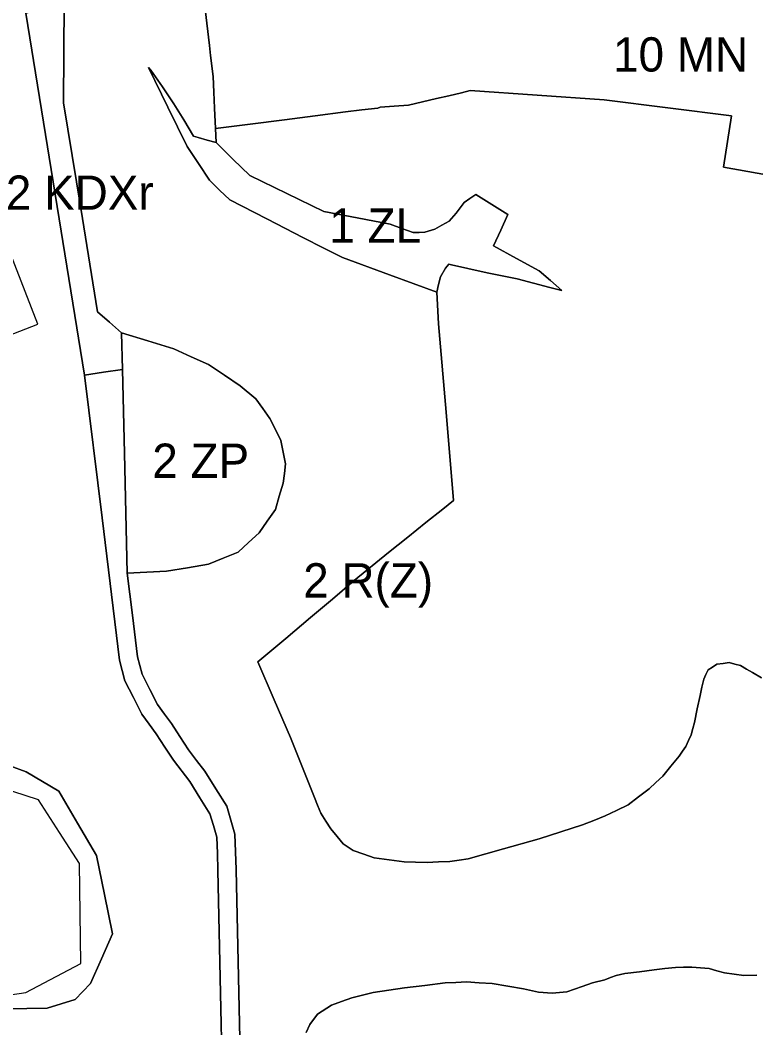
# Model space of a CAD drawing. Extents: x 7422252 to 7424226, y 5538569 to 5540380.
# Drawn here: x 7422919.5 to 7423241.3, y 5539103.9 to 5539544.8 of the extents above; entities that cross this region are included whole.
import ezdxf

# ---------------------------------------------------------------- set-up
doc = ezdxf.new("R2010")
doc.units = 0
for name, color, linetype in [('linie_rozgraniczajace', 7, 'Continuous'), ('linie_zabudowy_nieprzekraczalne', 7, 'Continuous'), ('oznaczenia_przeznaczen', 7, 'Continuous')]:
    doc.layers.add(name, color=color, linetype=linetype)

msp = doc.modelspace()

# ---------------------------------------------------------------- linework, layer by layer
at = {"layer": 'linie_rozgraniczajace'}
for points in [[(7423004.5, 5539506.3), (7423004.19, 5539513.23), (7423003.88, 5539520.17), (7423002.82, 5539529.33), (7423002.33, 5539533.66), (7423001.17, 5539543.48), (7423000.01, 5539553.3), (7422999.1, 5539558.79), (7422998.19, 5539564.28), (7422996.71, 5539573.16), (7422995.24, 5539582.03), (7422993.39, 5539589.32)], [(7422938.52, 5539508.56), (7422938.66, 5539530.56), (7422938.8, 5539552.56)], [(7423000.01, 5539553.3), (7423001.17, 5539543.48), (7423002.33, 5539533.66), (7423002.82, 5539529.33), (7423003.88, 5539520.17), (7423004.19, 5539513.23), (7423004.5, 5539506.3), (7423005, 5539497.42), (7423005.22, 5539491.17), (7423001.32, 5539492.3), (7422997.42, 5539493.44), (7422995.33, 5539494.06), (7422991.06, 5539501.14), (7422986.79, 5539508.21), (7422981.71, 5539515.52), (7422976.63, 5539522.84), (7422975.66, 5539524.01), (7422984.14, 5539506.72), (7422992.61, 5539489.43), (7422997.46, 5539482.11), (7423002.31, 5539474.78), (7423006.77, 5539470.43), (7423011.22, 5539466.09), (7423027.37, 5539457.82), (7423043.51, 5539449.56), (7423052.01, 5539445.2), (7423060.51, 5539440.85), (7423081.14, 5539433.34), (7423101.77, 5539425.82), (7423102.5, 5539411.86), (7423105.79, 5539373.21), (7423109.07, 5539334.55), (7423104.38, 5539330.82), (7423097.04, 5539325), (7423089.05, 5539318.54), (7423080.62, 5539311.82), (7423065.6, 5539299.62), (7423056.08, 5539291.39), (7423046.57, 5539283.46), (7423035.78, 5539274.23), (7423023.45, 5539264.05), (7423030.59, 5539247.47), (7423037.74, 5539230.89), (7423042.97, 5539217.8), (7423048.21, 5539204.7), (7423049.64, 5539201.26), (7423051.07, 5539197.82), (7423053.22, 5539194.37), (7423055.37, 5539190.92), (7423058.12, 5539187.65), (7423060.87, 5539184.39), (7423063.06, 5539182.95), (7423065.25, 5539181.51), (7423069.78, 5539179.9), (7423074.3, 5539178.3), (7423080.88, 5539177.41), (7423087.47, 5539176.52), (7423092.49, 5539176.39), (7423097.51, 5539176.26), (7423102.51, 5539176.51), (7423107.51, 5539176.75), (7423111.48, 5539177.32), (7423115.45, 5539177.89), (7423131, 5539182.28), (7423146.55, 5539186.66), (7423156.04, 5539189.67), (7423165.54, 5539192.67), (7423170.45, 5539194.67), (7423175.37, 5539196.67), (7423180.42, 5539199.06), (7423185.46, 5539201.44), (7423190.06, 5539204.99), (7423194.66, 5539208.54), (7423197.64, 5539211.3), (7423200.61, 5539214.07), (7423204.18, 5539218.43), (7423207.75, 5539222.8), (7423209.26, 5539224.9), (7423210.77, 5539227.01), (7423211.9, 5539229.58), (7423213.03, 5539232.14), (7423213.77, 5539234.81), (7423214.51, 5539237.49), (7423215.74, 5539243.4), (7423216.97, 5539249.32)], [(7422921.99, 5539547.81), (7422934.85, 5539468.63), (7422947.7, 5539389.45), (7422955.33, 5539327.07), (7422962.95, 5539264.69), (7422964.14, 5539260.23), (7422965.33, 5539255.76), (7422969.05, 5539248.43), (7422972.78, 5539241.1), (7422975.92, 5539236.81), (7422979.06, 5539232.51), (7422982.8, 5539226.73), (7422986.54, 5539220.95), (7422993.66, 5539211.67), (7422998.1, 5539204.6), (7423002.54, 5539197.53), (7423004.02, 5539192.46), (7423005.49, 5539187.39), (7423005.76, 5539180.15), (7423006.02, 5539172.9), (7423007.01, 5539125.74), (7423008, 5539078.57)], [(7423248.47, 5539476.61), (7423237.81, 5539478.49), (7423227.15, 5539480.37), (7423228.95, 5539491.62), (7423230.75, 5539502.87), (7423202.9, 5539506.36), (7423175.05, 5539509.86), (7423145.73, 5539511.95), (7423116.4, 5539514.04), (7423112.56, 5539512.95), (7423107.09, 5539511.68), (7423101.62, 5539510.41), (7423095.47, 5539508.99), (7423089.33, 5539507.56), (7423083.15, 5539507.1), (7423076.96, 5539506.64), (7423075.99, 5539506.28), (7423068.91, 5539505.45), (7423061.83, 5539504.62), (7423048.5, 5539502.85), (7423035.17, 5539501.08), (7423020.08, 5539499.25), (7423005, 5539497.42), (7423004.5, 5539506.3)], [(7423106.97, 5539438.01), (7423108.25, 5539437.72), (7423115.39, 5539436.08), (7423123.81, 5539434.15), (7423130.37, 5539432.83), (7423136.93, 5539431.52), (7423144.08, 5539429.67), (7423151.22, 5539427.83), (7423156.45, 5539426.55), (7423151.49, 5539430.81), (7423146.54, 5539435.07), (7423136.57, 5539440.53), (7423126.6, 5539445.99), (7423129.73, 5539452.83), (7423132.87, 5539459.68), (7423125.82, 5539464.11), (7423118.78, 5539468.55), (7423116.23, 5539466.79), (7423113.69, 5539465.03), (7423111.98, 5539462.7), (7423110.27, 5539460.37), (7423107.21, 5539456.77), (7423104.03, 5539455.01), (7423100.85, 5539453.26), (7423096.52, 5539451.95), (7423093.98, 5539451.92), (7423091.44, 5539451.88), (7423086.42, 5539453.66), (7423081.4, 5539455.44), (7423066.87, 5539458.24), (7423052.35, 5539461.05), (7423036.17, 5539468.93), (7423019.99, 5539476.81), (7423012.6, 5539483.99), (7423005.22, 5539491.17), (7423005, 5539497.42), (7423020.08, 5539499.25), (7423035.17, 5539501.08), (7423048.5, 5539502.85), (7423061.83, 5539504.62), (7423068.91, 5539505.45), (7423075.99, 5539506.28), (7423076.96, 5539506.64), (7423083.15, 5539507.1), (7423089.33, 5539507.56), (7423095.47, 5539508.99), (7423101.62, 5539510.41), (7423107.09, 5539511.68), (7423112.56, 5539512.95), (7423116.4, 5539514.04), (7423145.73, 5539511.95), (7423175.05, 5539509.86), (7423202.9, 5539506.36), (7423230.75, 5539502.87), (7423228.95, 5539491.62), (7423227.15, 5539480.37), (7423237.81, 5539478.49), (7423248.47, 5539476.61)], [(7423015.99, 5539079), (7423015, 5539126.07), (7423014.02, 5539173.13), (7423013.73, 5539180.9), (7423013.45, 5539188.67), (7423011.68, 5539194.76), (7423009.91, 5539200.84), (7423005.07, 5539208.54), (7423000.24, 5539216.24), (7422996.66, 5539220.9), (7422993.08, 5539225.56), (7422989.37, 5539231.3), (7422985.66, 5539237.05), (7422982.64, 5539241.17), (7422979.62, 5539245.3), (7422976.23, 5539251.97), (7422972.84, 5539258.63), (7422971.83, 5539262.42), (7422970.83, 5539266.21), (7422968.59, 5539284.48), (7422966.36, 5539302.75), (7422974.97, 5539303.23), (7422983.57, 5539303.71), (7422992.71, 5539305.21), (7423001.84, 5539306.71), (7423008.37, 5539309.36), (7423014.89, 5539312.02), (7423019.44, 5539316.26), (7423023.99, 5539320.51), (7423027.56, 5539325.61), (7423031.13, 5539330.71), (7423032.82, 5539336.47), (7423034.52, 5539342.24), (7423035.08, 5539346.43), (7423035.64, 5539350.62), (7423034.62, 5539355.73), (7423033.59, 5539360.85), (7423031.19, 5539365.67), (7423028.78, 5539370.49), (7423025.69, 5539374.8), (7423022.6, 5539379.11), (7423015.76, 5539384.84), (7423008.86, 5539389.49), (7423001.95, 5539394.14), (7422994.37, 5539397.52), (7422986.78, 5539400.9), (7422975.31, 5539404.44), (7422963.84, 5539407.98), (7422958.59, 5539412.56), (7422953.34, 5539417.13), (7422945.97, 5539462.52), (7422938.52, 5539508.56)], [(7423243.77, 5539256.98), (7423239.86, 5539259.34), (7423237.22, 5539260.87), (7423234.59, 5539262.4), (7423232.13, 5539263.06), (7423229.68, 5539263.73), (7423226.98, 5539263.34), (7423224.28, 5539262.96), (7423222.38, 5539261.73), (7423220.47, 5539260.49), (7423219.52, 5539258.51), (7423218.56, 5539256.52), (7423217.77, 5539252.92), (7423216.97, 5539249.32), (7423215.74, 5539243.4), (7423214.51, 5539237.49), (7423213.77, 5539234.81), (7423213.03, 5539232.14), (7423211.9, 5539229.58), (7423210.77, 5539227.01), (7423209.26, 5539224.9), (7423207.75, 5539222.8), (7423204.18, 5539218.43), (7423200.61, 5539214.07), (7423197.64, 5539211.3), (7423194.66, 5539208.54), (7423190.06, 5539204.99), (7423185.46, 5539201.44), (7423180.42, 5539199.06), (7423175.37, 5539196.67), (7423170.45, 5539194.67), (7423165.54, 5539192.67), (7423156.04, 5539189.67), (7423146.55, 5539186.66), (7423131, 5539182.28), (7423115.45, 5539177.89), (7423111.48, 5539177.32), (7423107.51, 5539176.75), (7423102.51, 5539176.51), (7423097.51, 5539176.26), (7423092.49, 5539176.39), (7423087.47, 5539176.52), (7423080.88, 5539177.41), (7423074.3, 5539178.3), (7423069.78, 5539179.9), (7423065.25, 5539181.51), (7423063.06, 5539182.95), (7423060.87, 5539184.39), (7423058.12, 5539187.65), (7423055.37, 5539190.92), (7423053.22, 5539194.37), (7423051.07, 5539197.82), (7423049.64, 5539201.26), (7423048.21, 5539204.7), (7423042.97, 5539217.8), (7423037.74, 5539230.89), (7423030.59, 5539247.47), (7423023.45, 5539264.05), (7423035.78, 5539274.23), (7423046.57, 5539283.46), (7423056.08, 5539291.39), (7423065.6, 5539299.62), (7423080.62, 5539311.82), (7423089.05, 5539318.54), (7423097.04, 5539325), (7423104.38, 5539330.82), (7423109.07, 5539334.55), (7423105.79, 5539373.21), (7423102.5, 5539411.86), (7423101.77, 5539425.82), (7423102.58, 5539429.14), (7423103.39, 5539432.45), (7423105.63, 5539436.29), (7423106.97, 5539438.01)], [(7423008, 5539078.57), (7423007.01, 5539125.74), (7423006.02, 5539172.9), (7423005.76, 5539180.15), (7423005.49, 5539187.39), (7423004.02, 5539192.46), (7423002.54, 5539197.53), (7422998.1, 5539204.6), (7422993.66, 5539211.67), (7422986.54, 5539220.95), (7422982.8, 5539226.73), (7422979.06, 5539232.51), (7422975.92, 5539236.81), (7422972.78, 5539241.1), (7422969.05, 5539248.43), (7422965.33, 5539255.76), (7422964.14, 5539260.23), (7422962.95, 5539264.69), (7422955.33, 5539327.07), (7422947.7, 5539389.45), (7422955.96, 5539390.69), (7422964.22, 5539391.93), (7422965.1, 5539355.37), (7422966.36, 5539302.75), (7422968.59, 5539284.48), (7422970.83, 5539266.21), (7422971.83, 5539262.42), (7422972.84, 5539258.63), (7422976.23, 5539251.97), (7422979.62, 5539245.3), (7422982.64, 5539241.17), (7422985.66, 5539237.05), (7422989.37, 5539231.3), (7422993.08, 5539225.56), (7422996.66, 5539220.9), (7423000.24, 5539216.24), (7423005.07, 5539208.54), (7423009.91, 5539200.84), (7423011.68, 5539194.76), (7423013.45, 5539188.67), (7423013.73, 5539180.9), (7423014.02, 5539173.13), (7423015, 5539126.07), (7423015.99, 5539079)], [(7423216.97, 5539249.32), (7423217.77, 5539252.92), (7423218.56, 5539256.52), (7423219.52, 5539258.51), (7423220.47, 5539260.49), (7423222.38, 5539261.73), (7423224.28, 5539262.96), (7423226.98, 5539263.34), (7423229.68, 5539263.73), (7423232.13, 5539263.06), (7423234.59, 5539262.4), (7423237.22, 5539260.87), (7423239.86, 5539259.34), (7423243.77, 5539256.98)], [(7422914.99, 5539218.51), (7422922.15, 5539215.84), (7422929.26, 5539211.66), (7422936.38, 5539207.48), (7422944.62, 5539193.39), (7422952.87, 5539179.31), (7422956.35, 5539162.18), (7422959.83, 5539145.05), (7422955.05, 5539134.15), (7422950.27, 5539123.24), (7422946.9, 5539119.78), (7422943.53, 5539116.33), (7422937.4, 5539114.41), (7422931.27, 5539112.49), (7422913.58, 5539112.2)], [(7422913.58, 5539112.2), (7422931.27, 5539112.49), (7422937.4, 5539114.41), (7422943.53, 5539116.33), (7422946.9, 5539119.78), (7422950.27, 5539123.24), (7422955.05, 5539134.15), (7422959.83, 5539145.05), (7422956.35, 5539162.18), (7422952.87, 5539179.31), (7422944.62, 5539193.39), (7422936.38, 5539207.48), (7422929.26, 5539211.66), (7422922.15, 5539215.84), (7422914.99, 5539218.51)], [(7422879.52, 5539113.04), (7422921.94, 5539119.36), (7422946.07, 5539132.08), (7422945.46, 5539175.81), (7422936.7, 5539189.32), (7422927.51, 5539203.72), (7422910.87, 5539209.09)], [(7423044.56, 5539101.89), (7423046.22, 5539105.36), (7423049.58, 5539109.92), (7423055.7, 5539113.83), (7423060.11, 5539115.46), (7423064.53, 5539117.08), (7423073.96, 5539119.37), (7423080.78, 5539120.38), (7423087.61, 5539121.4), (7423096.54, 5539122.48), (7423105.47, 5539123.57), (7423110.11, 5539123.78), (7423114.76, 5539123.99), (7423120.35, 5539123.64), (7423125.95, 5539123.28), (7423132.79, 5539122.09), (7423139.64, 5539120.91), (7423146.31, 5539119.48), (7423152.26, 5539119.01), (7423155.45, 5539119.33), (7423158.65, 5539119.66), (7423162.04, 5539120.81), (7423165.42, 5539121.96), (7423169.91, 5539123.54), (7423175.22, 5539124.94), (7423177.69, 5539125.87), (7423180.16, 5539126.79), (7423182.06, 5539127.25), (7423183.96, 5539127.71), (7423190.44, 5539128.48), (7423196.91, 5539129.25), (7423201.52, 5539129.81), (7423206.13, 5539130.37), (7423209.75, 5539130.39), (7423213.38, 5539130.41), (7423217.16, 5539130.11), (7423220.93, 5539129.81), (7423224.28, 5539128.88), (7423227.64, 5539127.95), (7423231.83, 5539127.41), (7423236.02, 5539126.88), (7423241.8, 5539127.02)], [(7423241.8, 5539127.02), (7423236.02, 5539126.88), (7423231.83, 5539127.41), (7423227.64, 5539127.95), (7423224.28, 5539128.88), (7423220.93, 5539129.81), (7423217.16, 5539130.11), (7423213.38, 5539130.41), (7423209.75, 5539130.39), (7423206.13, 5539130.37), (7423201.52, 5539129.81), (7423196.91, 5539129.25), (7423190.44, 5539128.48), (7423183.96, 5539127.71), (7423182.06, 5539127.25), (7423180.16, 5539126.79), (7423177.69, 5539125.87), (7423175.22, 5539124.94), (7423169.91, 5539123.54), (7423165.42, 5539121.96), (7423162.04, 5539120.81), (7423158.65, 5539119.66)], [(7423158.65, 5539119.66), (7423155.45, 5539119.33), (7423152.26, 5539119.01), (7423146.31, 5539119.48), (7423139.64, 5539120.91), (7423132.79, 5539122.09), (7423125.95, 5539123.28), (7423120.35, 5539123.64), (7423114.76, 5539123.99), (7423110.11, 5539123.78), (7423105.47, 5539123.57), (7423096.54, 5539122.48), (7423087.61, 5539121.4), (7423080.78, 5539120.38), (7423073.96, 5539119.37), (7423064.53, 5539117.08), (7423060.11, 5539115.46), (7423055.7, 5539113.83), (7423049.58, 5539109.92), (7423046.22, 5539105.36), (7423044.56, 5539101.89)]]:
    msp.add_lwpolyline(points, dxfattribs=at)
for points in [[(7422921.99, 5539547.81), (7422930.39, 5539550.19), (7422938.8, 5539552.56), (7422938.66, 5539530.56), (7422938.52, 5539508.56), (7422945.97, 5539462.52), (7422953.34, 5539417.13), (7422958.59, 5539412.56), (7422963.84, 5539407.98), (7422964.22, 5539391.93), (7422955.96, 5539390.69), (7422947.7, 5539389.45), (7422934.85, 5539468.63)], [(7422975.66, 5539524.01), (7422976.63, 5539522.84), (7422981.71, 5539515.52), (7422986.79, 5539508.21), (7422991.06, 5539501.14), (7422995.33, 5539494.06), (7422997.42, 5539493.44), (7423001.32, 5539492.3), (7423005.22, 5539491.17), (7423012.6, 5539483.99), (7423019.99, 5539476.81), (7423036.17, 5539468.93), (7423052.35, 5539461.05), (7423066.87, 5539458.24), (7423081.4, 5539455.44), (7423086.42, 5539453.66), (7423091.44, 5539451.88), (7423093.98, 5539451.92), (7423096.52, 5539451.95), (7423100.85, 5539453.26), (7423104.03, 5539455.01), (7423107.21, 5539456.77), (7423110.27, 5539460.37), (7423111.98, 5539462.7), (7423113.69, 5539465.03), (7423116.23, 5539466.79), (7423118.78, 5539468.55), (7423125.82, 5539464.11), (7423132.87, 5539459.68), (7423129.73, 5539452.83), (7423126.6, 5539445.99), (7423136.57, 5539440.53), (7423146.54, 5539435.07), (7423151.49, 5539430.81), (7423156.45, 5539426.55), (7423151.22, 5539427.83), (7423144.08, 5539429.67), (7423136.93, 5539431.52), (7423130.37, 5539432.83), (7423123.81, 5539434.15), (7423115.39, 5539436.08), (7423108.25, 5539437.72), (7423106.97, 5539438.01), (7423105.63, 5539436.29), (7423103.39, 5539432.45), (7423102.58, 5539429.14), (7423101.77, 5539425.82), (7423081.14, 5539433.34), (7423060.51, 5539440.85), (7423052.01, 5539445.2), (7423043.51, 5539449.56), (7423027.37, 5539457.82), (7423011.22, 5539466.09), (7423006.77, 5539470.43), (7423002.31, 5539474.78), (7422997.46, 5539482.11), (7422992.61, 5539489.43), (7422984.14, 5539506.72)], [(7422966.36, 5539302.75), (7422965.1, 5539355.37), (7422964.22, 5539391.93), (7422963.84, 5539407.98), (7422975.31, 5539404.44), (7422986.78, 5539400.9), (7422994.37, 5539397.52), (7423001.95, 5539394.14), (7423008.86, 5539389.49), (7423015.76, 5539384.84), (7423022.6, 5539379.11), (7423025.69, 5539374.8), (7423028.78, 5539370.49), (7423031.19, 5539365.67), (7423033.59, 5539360.85), (7423034.62, 5539355.73), (7423035.64, 5539350.62), (7423035.08, 5539346.43), (7423034.52, 5539342.24), (7423032.82, 5539336.47), (7423031.13, 5539330.71), (7423027.56, 5539325.61), (7423023.99, 5539320.51), (7423019.44, 5539316.26), (7423014.89, 5539312.02), (7423008.37, 5539309.36), (7423001.84, 5539306.71), (7422992.71, 5539305.21), (7422983.57, 5539303.71), (7422974.97, 5539303.23)]]:
    msp.add_lwpolyline(points, close=True, dxfattribs=at)
at = {"layer": 'linie_zabudowy_nieprzekraczalne'}
msp.add_lwpolyline([(7422836.33, 5539507.26), (7422880.53, 5539393.63), (7422927.18, 5539411.77), (7422882.98, 5539525.41), (7422836.33, 5539507.26)], dxfattribs=at)

# ---------------------------------------------------------------- texts
at = {"layer": 'oznaczenia_przeznaczen'}
for s, p in [('10 MN', (7423178.87, 5539522.26)), ('2 KDXr', (7422913.24, 5539461.78)), ('1 ZL', (7423054.74, 5539447.36)), ('2 ZP', (7422977.3, 5539344.51)), ('2 R(Z)', (7423043.32, 5539292.17))]:
    msp.add_text(s, height=15, dxfattribs=at).set_placement(p)

doc.saveas('drawing.dxf')
